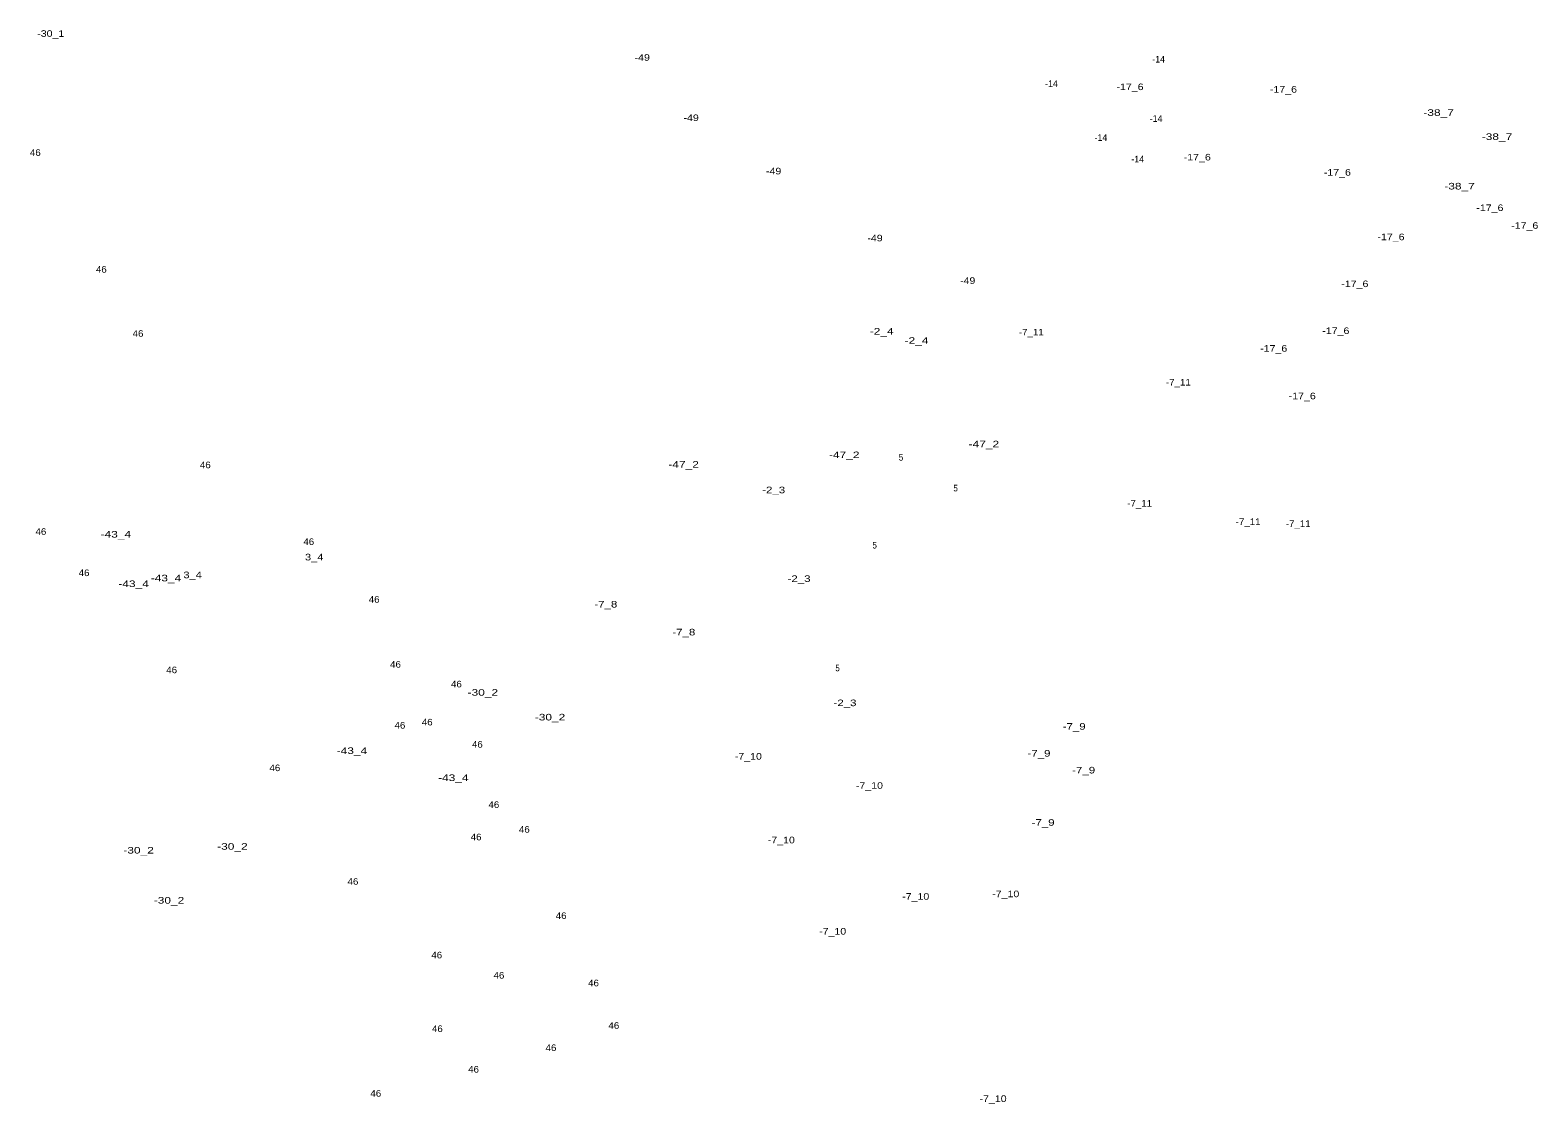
# Model space of a CAD drawing. Extents: x -663241 to -661169, y -1003538 to -1000899.
# Drawn here: x -662479 to -661565, y -1003538 to -1002888 of the extents above; entities that cross this region are included whole.
import ezdxf
from ezdxf.enums import TextEntityAlignment as Align

# ---------------------------------------------------------------- set-up
doc = ezdxf.new("R2010")
doc.units = 0
doc.header["$LTSCALE"] = 1.6
doc.layers.add('24', color=7, linetype='Continuous')

msp = doc.modelspace()

# ---------------------------------------------------------------- texts
at = {"layer": '24'}
for s, width, p in [('-30_1', 1.2, (-662466.079, -1002891.85)), ('-49', 1.2, (-662107.801, -1002906.36)), ('-17_6', 1.2, (-661812.34, -1002924.14)), ('-17_6', 1.2, (-661719.41, -1002925.68)), ('-49', 1.2, (-662078.201, -1002942.9)), ('-38_7', 1.35, (-661625.43, -1002939.73)), ('-38_7', 1.35, (-661590.06, -1002954.35)), ('46', 1.1, (-662475.43, -1002963.99)), ('-17_6', 1.2, (-661771.63, -1002966.78)), ('-49', 1.2, (-662028.211, -1002975.21)), ('-17_6', 1.2, (-661686.77, -1002976)), ('-38_7', 1.35, (-661612.74, -1002984.35)), ('-17_6', 1.2, (-661594.37, -1002997.43)), ('-17_6', 1.2, (-661573.25, -1003008.18)), ('-49', 1.2, (-661966.811, -1003015.82)), ('-17_6', 1.2, (-661654.28, -1003015.1)), ('46', 1.1, (-662435.45, -1003034.76)), ('-49', 1.2, (-661910.681, -1003041.59)), ('-17_6', 1.2, (-661676.17, -1003043.52)), ('46', 1.1, (-662413.22, -1003073.65)), ('-2_4', 1.35, (-661962.78, -1003072.32)), ('-7_11', 1.1, (-661872.15, -1003072.81)), ('-17_6', 1.2, (-661687.69, -1003071.95)), ('-2_4', 1.35, (-661941.66, -1003077.89)), ('-17_6', 1.2, (-661725.32, -1003082.68)), ('-7_11', 1.1, (-661783.051, -1003103.16)), ('-17_6', 1.2, (-661708.04, -1003111.49)), ('-47_2', 1.35, (-661985.459, -1003147.18)), ('-47_2', 1.35, (-661900.88, -1003140.64)), ('46', 1.1, (-662372.47, -1003153.27)), ('-47_2', 1.35, (-662082.74, -1003152.95)), ('5', 0.9, (-661951.049, -1003148.66)), ('-2_3', 1.3, (-662028.199, -1003168.43)), ('5', 0.9, (-661917.99, -1003167.33)), ('-7_11', 1.1, (-661806.49, -1003176.54)), ('-7_11', 1.1, (-661740.821, -1003187.67)), ('-7_11', 1.1, (-661710.481, -1003188.83)), ('46', 1.1, (-662472.05, -1003193.65)), ('-43_4', 1.35, (-662426.67, -1003195.31)), ('46', 1.1, (-662309.8, -1003199.8)), ('5', 0.9, (-661967.01, -1003201.93)), ('3_4', 1.25, (-662306.52, -1003209.15)), ('46', 1.1, (-662445.9, -1003218.65)), ('3_4', 1.25, (-662380.15, -1003219.92)), ('-43_4', 1.35, (-662415.9, -1003225.31)), ('-43_4', 1.35, (-662396.29, -1003221.85)), ('-2_3', 1.3, (-662012.84, -1003222.21)), ('46', 1.1, (-662270.2, -1003234.8)), ('-7_8', 1.3, (-662129.86, -1003237.7)), ('-7_8', 1.3, (-662082.62, -1003254.61)), ('46', 1.1, (-662257.28, -1003274.15)), ('46', 1.1, (-662392.85, -1003277.5)), ('5', 0.9, (-661989.5, -1003276.35)), ('46', 1.1, (-662220.37, -1003286.08)), ('-30_2', 1.35, (-662204.37, -1003291.14)), ('-2_3', 1.3, (-661985, -1003297.47)), ('46', 1.1, (-662254.59, -1003311.08)), ('46', 1.1, (-662238.06, -1003309.15)), ('-30_2', 1.35, (-662163.669, -1003306.13)), ('-7_9', 1.3, (-661846.191, -1003311.75)), ('-43_4', 1.35, (-662283.64, -1003326.46)), ('46', 1.1, (-662207.68, -1003322.61)), ('-7_10', 1.2, (-662043.541, -1003329.88)), ('-7_9', 1.3, (-661867.5, -1003328.08)), ('46', 1.1, (-662330.33, -1003336.84)), ('-7_9', 1.3, (-661840.431, -1003338.26)), ('-43_4', 1.35, (-662222.24, -1003342.85)), ('-7_10', 1.2, (-661970.201, -1003347.55)), ('46', 1.1, (-662197.69, -1003359.15)), ('46', 1.1, (-662179.23, -1003374.15)), ('-7_9', 1.3, (-661865.01, -1003369.95)), ('-30_2', 1.35, (-662356.059, -1003384.49)), ('46', 1.1, (-662208.45, -1003378.77)), ('-7_10', 1.2, (-662023.571, -1003380.59)), ('-30_2', 1.35, (-662412.89, -1003386.79)), ('46', 1.1, (-662283.04, -1003405.69)), ('-30_2', 1.35, (-662394.459, -1003417.14)), ('-7_10', 1.2, (-661942.16, -1003414.78)), ('-7_10', 1.2, (-661887.63, -1003413.24)), ('46', 1.1, (-662156.93, -1003426.46)), ('-7_10', 1.2, (-661992.471, -1003435.91)), ('46', 1.1, (-662232.29, -1003450.31)), ('46', 1.1, (-662194.61, -1003462.61)), ('46', 1.1, (-662137.32, -1003467.23)), ('46', 1.1, (-662125.02, -1003493)), ('46', 1.1, (-662231.9, -1003494.92)), ('46', 1.1, (-662163.08, -1003506.46)), ('46', 1.1, (-662209.99, -1003519.54)), ('46', 1.1, (-662269.2, -1003534.15)), ('-7_10', 1.2, (-661895.311, -1003537.33))]:
    msp.add_text(s, height=4, dxfattribs=dict(at, width=width)).set_placement(p, align=Align.CENTER)
for p in [(-661795.03, -1002907.41), (-661859.93, -1002922.24), (-661796.56, -1002943.37), (-661829.97, -1002954.89), (-661807.7, -1002967.95)]:
    msp.add_text('-14', height=4, dxfattribs=at).set_placement(p, align=Align.CENTER)

doc.saveas('drawing.dxf')
